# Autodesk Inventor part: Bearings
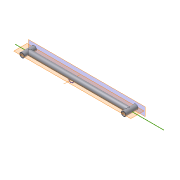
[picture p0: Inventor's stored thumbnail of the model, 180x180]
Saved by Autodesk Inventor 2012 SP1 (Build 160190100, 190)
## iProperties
Created: 2006-03
Part Number: Bearings
Document SubType Name: Modeling
Material: Stainless Steel, 440C
Mass: 435.608 g
Surface Area: 566.387 cm^2
Volume: 56.2075 cm^3
Density: 7.75 g/cm^3
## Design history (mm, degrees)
sketch "Sketch1"
  geometry: L1 (0, -12)-(0, 16) reference; L2 (-66, 0)-(242, 0) reference; C1 r 10 at (210, 0); 1 further point
  constraints: 1 centre point
  dimensions: "d3" = 20 diameter of C1; "d6" = 210 distance of C1.centre point (0, 0)
extrude "Extrusion1" new body sketch "Sketch1" stored distance "d4" = 50; taper "d5" = 0 deg
sketch "Sketch3"
  geometry: C1 r 10 at (0, 0); 1 further point
  constraints: 1 centre point, 1 coincident
  dimensions: "d8" = 20 diameter of C1
extrude "Extrusion2" join sketch "Sketch3" stored distance "d9" = 50; taper "d10" = 0 deg
mirror "Mirror1"
shell "Shell1" dims "d11" = 2
sketch "Sketch4"
  geometry: L1 (-352, 0)-(264, 0) reference; C1 r 10 at (32.287, -11.821); A1 r 8 centre (-210, 0) between (-210, -8) and (-210, 8) reference; 1 further point
  constraints: 1 centre point
  dimensions: "d12" = 11.821 distance from line of C1.centre L1; "d13" = 242.575 distance of C1.centre A1.centre; "d14" = 20 diameter of C1
workaxis "Work Axis1"
node "Ref"
sketch "Sketch5"
  geometry: C1 r 8 at (210, 0) reference; C2 r 8 at (-210, 0) reference; 1 further point
node "Bearing"
node "Ref_Wiper"
body "Solid1"
other parameters: "d16" = 0, "d20" = 8
